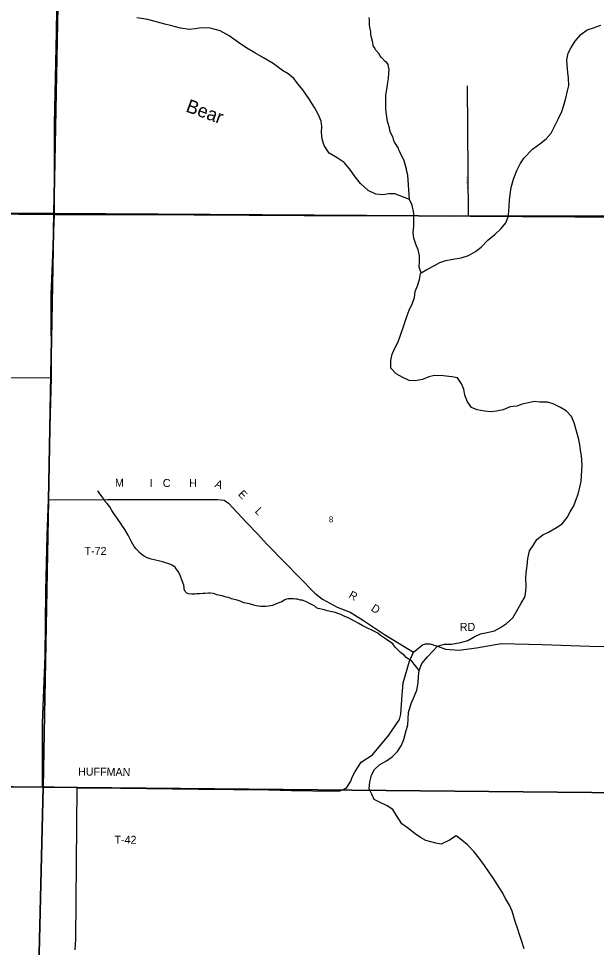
# Model space of a CAD drawing. Extents: x 1312308 to 1684953, y 460642 to 865172.
# Drawn here: x 1448582 to 1454002, y 628989 to 637693 of the extents above; entities that cross this region are included whole.
import ezdxf

# ---------------------------------------------------------------- set-up
doc = ezdxf.new("R2010")
doc.units = 0
for name, color, linetype in [('GM_X_County_Road', 7, 'Continuous'), ('GM_X_Minor_River', 7, 'Continuous'), ('GM_X_Minor_River_Text', 7, 'Continuous'), ('GM_X_Section', 7, 'Continuous'), ('GM_X_Section_Text', 7, 'Continuous'), ('GM_X_Township_Road', 7, 'Continuous'), ('GM_X_Township_Road_Text', 7, 'Continuous'), ('GM_X_Township_Subdivision', 7, 'Continuous'), ('GM_X_Township_Subdivision_Text', 7, 'Continuous')]:
    doc.layers.add(name, color=color, linetype=linetype)

msp = doc.modelspace()

# ---------------------------------------------------------------- linework, layer by layer
at = {"layer": 'GM_X_County_Road'}
msp.add_lwpolyline([(1449111.5, 628966.9), (1449119.1, 629065.1), (1449124.9, 629779), (1449130.7, 630483.3), (1448806.5, 630494.9), (1448805.5, 631091.4), (1448832.9, 631717.5), (1448837.9, 632325.7), (1448850.4, 632851.4), (1448862.8, 633183), (1448874.2, 633752.5), (1448890.2, 634329.9), (1448888.3, 635104.4), (1448919.3, 635858), (1448920.4, 636705.2), (1448937.9, 637564.6), (1448948.5, 638213.8), (1448958.1, 638814.9), (1448971.3, 639666.4), (1448984.3, 640325.5), (1449028.3, 641206.2)], dxfattribs=at)
at = {"layer": 'GM_X_Minor_River'}
for points in [[(1452359.5, 635311.4), (1452338.6, 635363.8), (1452342, 635413.9), (1452341.5, 635468.1), (1452329, 635526.6), (1452308.3, 635579.4), (1452289.7, 635634.1), (1452283.2, 635688.4), (1452288.8, 635746.5), (1452290.6, 635814.7), (1452290.1, 635868.9), (1452274, 635943.6), (1452247.4, 635998.5), (1452112.2, 636050.4), (1452053.9, 636050.1), (1451999.4, 636041.6), (1451933.2, 636047.5), (1451859.8, 636081.6), (1451789.2, 636147.8), (1451740.7, 636211.4), (1451690.4, 636281), (1451635.8, 636342.8), (1451570.7, 636388.7), (1451495.5, 636433), (1451449.3, 636504.5), (1451430.8, 636563.2), (1451422.5, 636629.7), (1451428, 636681.7), (1451421.3, 636732.1), (1451394.8, 636791), (1451358.4, 636858.2), (1451304.5, 636944), (1451248.4, 637025.9), (1451205.6, 637077.2), (1451162.8, 637130.6), (1451111.8, 637174.2), (1451056.4, 637205.8), (1450969.8, 637272.5), (1450878.7, 637325.2), (1450799.6, 637371.6), (1450724.5, 637415.8), (1450643.5, 637470.3), (1450558.8, 637530.8), (1450471.7, 637579.4), (1450379.9, 637604.1), (1450293.6, 637606.5), (1450239.1, 637598), (1450186.6, 637591.4), (1450102.5, 637601.8), (1450006.7, 637626.6), (1449954.9, 637642.1), (1449795.3, 637684.7), (1449691.2, 637699.6)], [(1452247.4, 635998.5), (1452234.5, 636225.8), (1452223.3, 636260.2), (1452221.9, 636282.4), (1452210.7, 636316.8), (1452197.7, 636361.3), (1452188.2, 636381.7), (1452151.9, 636454.9), (1452146.4, 636477.2), (1452109.7, 636536.3), (1452100.2, 636558.7), (1452096.7, 636578.9), (1452071.7, 636625.7), (1452064.3, 636648), (1452060.7, 636668.2), (1452042.1, 636726.9), (1452040.7, 636749.1), (1452030.3, 636815.7), (1452027.2, 636851.9), (1452026.1, 636884.1), (1452025.9, 636954.4), (1452026.3, 636972.5), (1452031, 636996.5), (1452038.4, 637048.6), (1452043, 637074.6), (1452048.1, 637112.7), (1452050.5, 637130.7), (1452055.8, 637180.8), (1452056.7, 637215), (1452053.5, 637245.2), (1452049.9, 637261.4), (1452036.3, 637279.8), (1452020.5, 637292.2), (1451985.2, 637329.3), (1451969.6, 637347.8), (1451963.9, 637362), (1451928.6, 637399), (1451919.2, 637421.3), (1451909.5, 637437.7), (1451904.2, 637467.9), (1451891.4, 637516.5), (1451886.1, 637544.8), (1451884.7, 637568.9), (1451875.8, 637613.3), (1451874.2, 637631.5), (1451874.7, 637649.5), (1451873.6, 637683.7), (1451872.1, 637703.9)], [(1452359.5, 635311.4), (1452410.4, 635341.7), (1452483.8, 635379.8), (1452534.7, 635406.5), (1452589.5, 635425), (1452654.2, 635439.2), (1452732.9, 635451), (1452803.9, 635473.1), (1452867.2, 635511.5), (1452920.6, 635552.1), (1452984.6, 635616.6), (1453050.4, 635670.9), (1453110.2, 635725.4), (1453153.8, 635778.4), (1453175.4, 635833.9), (1453180.8, 635883.9), (1453184.2, 635936), (1453187.7, 635990.1), (1453193.2, 636044.1), (1453203, 636110.1), (1453225.2, 636187.7), (1453255.6, 636269.1), (1453287.4, 636330.5), (1453325.1, 636387.6), (1453403.7, 636467.7), (1453471.4, 636519.9), (1453531, 636566.4), (1453576.6, 636619.3), (1453606.3, 636676.7), (1453642.5, 636749.9), (1453676.6, 636823.2), (1453696.4, 636882.8), (1453714.2, 636948.6), (1453730.1, 637014.3), (1453743.6, 637066.1), (1453739.4, 637134.5), (1453732.8, 637188.8), (1453726.6, 637255.2), (1453724, 637307.5), (1453735.7, 637369.4), (1453765.3, 637420.7), (1453803.1, 637481.8), (1453857.1, 637544.5), (1453916.5, 637587), (1453973.3, 637605.5), (1454044.3, 637631.6)], [(1452829.4, 634049.6), (1452792.6, 634100.8), (1452768.2, 634163.7), (1452759.7, 634220.2), (1452736.9, 634271), (1452700.3, 634326.2), (1452646.3, 634335.7), (1452564.1, 634344), (1452483.8, 634348.3), (1452429.2, 634335.8), (1452372.3, 634311.3), (1452301.6, 634297.3), (1452245.4, 634300.8), (1452185.9, 634330.6), (1452124.5, 634362.4), (1452073.7, 634418), (1452073.6, 634488.3), (1452087.3, 634548.1), (1452113.2, 634611.6), (1452142.8, 634664.9), (1452168.8, 634734.5), (1452186.3, 634788.1), (1452203.9, 634843.8), (1452227.8, 634909.4), (1452247.3, 634961), (1452277.2, 635026.4), (1452296.7, 635080), (1452302.2, 635134.1), (1452323.8, 635189.6), (1452341.5, 635247.3), (1452353.1, 635303.2), (1452359.5, 635311.4)], [(1452852.7, 629888.5), (1452792.1, 629950.4), (1452741.1, 629994), (1452685.9, 630035.7), (1452624.5, 629993.3), (1452547.1, 629955.3), (1452495.1, 629964.8), (1452403.4, 629991.5), (1452351.9, 630019), (1452300.6, 630054.6), (1452231.7, 630108.8), (1452176.5, 630146.4), (1452128.4, 630226.1), (1452093.7, 630281.2), (1452040.4, 630316.9), (1451969, 630351), (1451917.4, 630374.5), (1451896.7, 630425.3), (1451869.9, 630476.2), (1451877.7, 630540.2), (1451891.4, 630602.1), (1451919.1, 630657.5), (1451970.5, 630702.2), (1452033.8, 630736.5), (1452085, 630773.2), (1452136.6, 630823.9), (1452170.3, 630879.2), (1452196, 630936.7), (1452214, 631008.4), (1452231.9, 631074.2), (1452237.4, 631130.2), (1452239.1, 631190.3), (1452265.4, 631273.9), (1452295.6, 631347.3), (1452317.1, 631398.9), (1452331, 631466.7), (1452334.7, 631528.8), (1452340.2, 631584.9), (1452366.1, 631650.4), (1452418, 631711.1), (1452465.6, 631762), (1452511.2, 631812.9), (1452576.1, 631831.1), (1452644.4, 631831.2), (1452727.2, 631844.9), (1452796, 631865.1), (1452855.3, 631899.5), (1452916.3, 631927.9), (1452976.9, 631940.2), (1453047.7, 631954.3), (1453102.8, 631986.9), (1453160.1, 632025.4), (1453217.8, 632077.9), (1453264.3, 632158.9), (1453296, 632216.2), (1453329.6, 632269.5), (1453341.1, 632323.3), (1453342.7, 632381.5), (1453340.3, 632441.8), (1453343.8, 632497.8), (1453353.7, 632565.8), (1453357.6, 632633.9), (1453375.6, 632703.7), (1453409.1, 632754.9), (1453444.8, 632810.1), (1453500.3, 632854.7), (1453551.2, 632881.3), (1453626.7, 632923.4), (1453681.9, 632957.9), (1453727.8, 633018.8), (1453755.3, 633070.2), (1453791.1, 633127.4), (1453808.5, 633179.1), (1453832.2, 633236.7), (1453846, 633300.5), (1453857.6, 633356.4), (1453863, 633408.4), (1453867.8, 633510.6), (1453862.1, 633595.1), (1453853.4, 633647.5), (1453846.8, 633699.8), (1453834.4, 633760.4), (1453816.1, 633825.1), (1453792.2, 633906.1), (1453769.6, 633964.9), (1453718.9, 634018.5), (1453665.4, 634048.1), (1453596, 634084.2), (1453544.2, 634097.7), (1453469.9, 634099.8), (1453417.7, 634105.3), (1453365.1, 634092.7), (1453306.5, 634078.3), (1453255.7, 634059.7), (1453193.3, 634055.4), (1453128.2, 634025.1), (1453065.5, 634012.9), (1453011.2, 634008.4), (1452953, 634014), (1452885.1, 634028), (1452829.4, 634049.6)], [(1449807.1, 632634.4), (1449783.1, 632643), (1449763.3, 632653.6), (1449741.5, 632668.2), (1449721.8, 632684.7), (1449684.6, 632723.8), (1449667.1, 632746.4), (1449653.5, 632768.8), (1449638.1, 632795.3), (1449624.7, 632821.8), (1449609.4, 632852.3), (1449578.6, 632905.3), (1449551.4, 632946.2), (1449539.8, 632962.5), (1449518.4, 632993.2), (1449506.8, 633011.6), (1449481.5, 633044.3), (1449456.4, 633083.2), (1449437.1, 633117.8), (1449413.8, 633148.5), (1449392.2, 633169.1), (1449384.5, 633185.4), (1449365, 633210), (1449343.7, 633240.7), (1449324.2, 633267.2)], [(1452340.2, 631584.9), (1452270, 631670), (1452256.2, 631680.4), (1452236.4, 631692.9), (1452218.6, 631705.4), (1452202.9, 631723.9), (1452163.4, 631753), (1452114.4, 631802.4), (1452093.1, 631835.1), (1452033.7, 631872.8), (1451976.3, 631912.3), (1451950.7, 631935.1), (1451907, 631954.2), (1451841.4, 631988), (1451805.6, 632004.9), (1451766, 632028), (1451732.2, 632046.9), (1451692.5, 632068), (1451674.6, 632076.5), (1451634.7, 632091.5), (1451605, 632108.3), (1451585, 632114.8), (1451541.1, 632130), (1451521.1, 632134.5), (1451477.1, 632143.6), (1451451.1, 632152.3), (1451435.2, 632156.7), (1451407.1, 632161.4), (1451393.1, 632165.7), (1451377.2, 632172.2), (1451361.4, 632186.6), (1451347.5, 632193), (1451317.8, 632209.8), (1451303.8, 632216.2), (1451282, 632228.8), (1451268, 632233.1), (1451242.1, 632241.8), (1451228.1, 632244.1), (1451198.1, 632250.9), (1451182, 632251.3), (1451161.9, 632253.8), (1451139.8, 632256.3), (1451125.8, 632256.7), (1451111.6, 632255), (1451095.4, 632251.4), (1451073.1, 632243.9), (1451050.5, 632228.3), (1451032.2, 632220.7), (1450997.7, 632209.5), (1450963.1, 632194.3), (1450944.9, 632188.7), (1450928.7, 632185.1), (1450902.5, 632183.7), (1450870.2, 632182.5), (1450854.1, 632182.9), (1450834.1, 632185.4), (1450814.1, 632189.9), (1450800, 632192.2), (1450768.1, 632203), (1450748.1, 632207.5), (1450696.1, 632218.9), (1450660.2, 632233.8), (1450632.3, 632242.5), (1450578.3, 632255.9), (1450550.4, 632266.6), (1450530.3, 632271.1), (1450492.4, 632282.1), (1450474.4, 632286.6), (1450440.4, 632293.4), (1450420.4, 632301.9), (1450406.4, 632304.3), (1450378.3, 632307), (1450362.2, 632307.4), (1450330, 632306.2), (1450313.9, 632306.5), (1450283.6, 632303.3), (1450251.4, 632302), (1450235.2, 632300.4), (1450207, 632299.1), (1450176.9, 632301.8), (1450158.9, 632308.3), (1450143.3, 632324.8), (1450135.7, 632345), (1450134.1, 632361.2), (1450130.7, 632383.3), (1450115.6, 632423.9), (1450100.6, 632466.5), (1450095.1, 632484.7), (1450079.6, 632511.2), (1450060.2, 632537.8), (1450050.5, 632552.1), (1450034.7, 632562.6), (1450018.8, 632571), (1450000.9, 632579.5), (1449980.9, 632586), (1449959, 632592.5), (1449931, 632601.3), (1449907, 632607.9), (1449855, 632621.2), (1449827, 632627.9), (1449807.1, 632634.4)], [(1453324.3, 628975.9), (1453302, 629044.8), (1453283.5, 629101.5), (1453263.2, 629170.3), (1453244.6, 629223.1), (1453227.9, 629275.7), (1453213.3, 629328.3), (1453186.7, 629385.3), (1453148.2, 629448.6), (1453117.6, 629505.7), (1453075.3, 629575.1), (1453030.9, 629642.6), (1452992.2, 629695.9), (1452951.6, 629755.2), (1452901.2, 629824.9), (1452852.7, 629888.5)]]:
    msp.add_lwpolyline(points, dxfattribs=at)
at = {"layer": 'GM_X_Section'}
for points in [[(1449014.8, 641205.3), (1448913.4, 635865.7), (1443600.1, 635884.6), (1443676.3, 641258.7)], [(1454339.4, 641156.2), (1454286.2, 635831.7), (1448913.4, 635865.7), (1449014.8, 641205.3), (1454041.4, 641154.2)], [(1443600.1, 635884.6), (1448913.4, 635865.7), (1448813.2, 630490.1), (1443490.8, 630551.1)], [(1448913.4, 635865.7), (1454286.2, 635831.7), (1454281.7, 630438.2), (1448813.2, 630490.1)], [(1443490.8, 630551.1), (1448813.2, 630490.1), (1448684.1, 625165.1), (1443369.8, 625229.9), (1443469, 629861.6)], [(1448813.2, 630490.1), (1454281.7, 630438.2), (1454204, 625082.2), (1448684.1, 625165.1)]]:
    msp.add_lwpolyline(points, close=True, dxfattribs=at)
at = {"layer": 'GM_X_Township_Road'}
for points in [[(1443600.4, 635879.1), (1444138.1, 635873.5), (1444236.3, 635878.6), (1444619.2, 635876.3), (1445162.4, 635875.1), (1446194.1, 635876.3), (1447163, 635872.9), (1448238, 635862.6), (1448919.3, 635858)], [(1448919.3, 635858), (1450226, 635854.6), (1451260, 635846.6), (1452208.3, 635846.6), (1452634, 635842.1), (1452802.9, 635846.6), (1453362.1, 635844.3), (1454278.5, 635845.5)], [(1448180.4, 634327.6), (1448890.2, 634329.9)], [(1448862.8, 633183), (1449416.3, 633186.4), (1450046.3, 633186.4), (1450446.9, 633185.3), (1450509.6, 633179.6), (1450551.9, 633153.3), (1450718.5, 632969.6), (1450822.3, 632865.7), (1450911.3, 632767.6), (1451090.5, 632586.1), (1451206.9, 632464), (1451360.5, 632307.6), (1451433.7, 632252.8), (1451571.3, 632178.7), (1451693.5, 632129.6), (1451816.6, 632052.6), (1452012.9, 631920.8), (1452287.1, 631756.3)], [(1449130.7, 630483.3), (1449537.7, 630481.4), (1450269.4, 630470.3), (1450930.5, 630464.6), (1451143.6, 630460.7), (1451540, 630452.1), (1451595.8, 630455.4), (1451622.8, 630464.6), (1451660.3, 630488.6), (1451697.3, 630545.9), (1451712.2, 630582.9), (1451740.6, 630638.2), (1451794.5, 630723.4), (1451901.5, 630793.3), (1452055.9, 630978.3), (1452126.4, 631083.1), (1452155.3, 631124.1), (1452166.9, 631175.1), (1452175.5, 631310.8), (1452189, 631469.6), (1452247.7, 631672.6), (1452287.1, 631756.3), (1452369.9, 631823.6), (1452399.7, 631833.3), (1452440.1, 631833.3), (1452511.3, 631811.1), (1452585.4, 631784.2), (1452712.4, 631774.6), (1452877.9, 631797.7), (1453108.8, 631836.1), (1453491.8, 631826.5), (1453940.2, 631811.1), (1454281.7, 631805.4)], [(1448355.2, 630492.9), (1448806.5, 630494.9)]]:
    msp.add_lwpolyline(points, dxfattribs=at)
at = {"layer": 'GM_X_Township_Subdivision'}
msp.add_lwpolyline([(1452802.9, 635846.6), (1452792.4, 637061.9)], dxfattribs=at)

# ---------------------------------------------------------------- texts
at = {"layer": 'GM_X_Minor_River_Text'}
msp.add_text('Bear', height=124.99, rotation=340.00861, dxfattribs=at).set_placement((1450143.1, 636823.9))
at = {"layer": 'GM_X_Section_Text'}
msp.add_text('8', height=55.3, rotation=0.00001, dxfattribs=at).set_placement((1451492.9, 632972.3))
at = {"layer": 'GM_X_Township_Road_Text'}
for s, rotation, p in [('M', 359.73712, (1449486.2, 633305.7)), ('I', 359.7346, (1449811.7, 633304.2)), ('C', 359.7346, (1449934.9, 633303.6)), ('H', 359.49, (1450181, 633302.5)), ('A', 339.22141, (1450417.6, 633305.3)), ('E', 314.63333, (1450636.1, 633230)), ('L', 313.83631, (1450793, 633071.1)), ('T-72', 0.00001, (1449200.5, 632666.9)), ('R', 329.87898, (1451671.6, 632270.7)), ('D', 327.09602, (1451881.5, 632149.1)), ('RD', 0.00001, (1452720.5, 631954.9)), ('HUFFMAN', 359.4399, (1449140.1, 630599.8)), ('T-42', 359.65289, (1449481.6, 629960.9))]:
    msp.add_text(s, height=75, rotation=rotation, dxfattribs=at).set_placement(p)
at = {"layer": 'GM_X_Township_Subdivision_Text'}
msp.add_text('KREITZER DR', height=12.5, rotation=90.63625, dxfattribs=at).set_placement((1452799.7, 636095.9))

doc.saveas('drawing.dxf')
